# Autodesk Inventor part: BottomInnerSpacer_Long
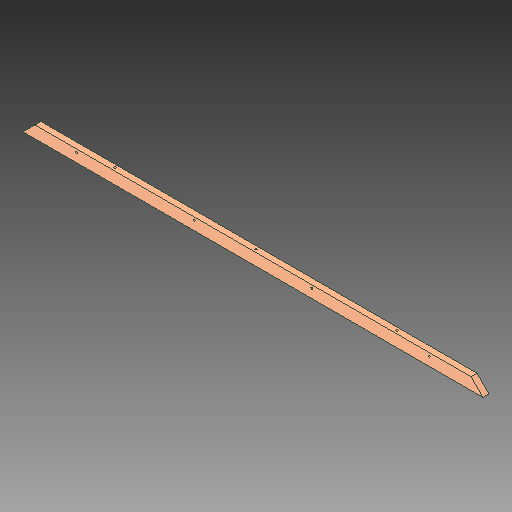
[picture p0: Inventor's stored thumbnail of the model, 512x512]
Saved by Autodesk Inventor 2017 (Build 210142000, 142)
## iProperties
Created: 2017-05
Part Number: BottomInnerSpacer_Long
Material: Generic
Document SubType Name: Modeling
Designer: Savy
Density: 1 g/cm^3
Appearance: Default
Mass: 305.662 g
Surface Area: 749.129 cm^2
Volume: 305.662 cm^3
Author: Savy
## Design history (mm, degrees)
feature "SOLID1"
body "Solid1"
